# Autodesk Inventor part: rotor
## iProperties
Company: Autodesk, Inc.
Shininess: 64.0
Length Units: 11269
Angle Units: 11279
Time Units: 11290
Mass Units: 11283
Length Display Precision: 3
Angle Display Precision: 2
Compacted: True
Part Number: rotor
Document SubType Name: Modeling
Created: 2003-11
Catalog Web Link: www.autodesk.com
Vendor: Autodesk, Inc.
Designer: Administrator
Manufacturer: Standard
Standards Organization: Custom
Density: 1 g/cm^3
Density: 0.0
Volumn: 0.0
Area: 0.0
PropertySet Name: Model Information
Control State: 0
Master: False
Checked Out: False
Author: Administrator
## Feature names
1. Extrusion1
2. Extrusion2
3. Extrusion4
4. Extrusion5
